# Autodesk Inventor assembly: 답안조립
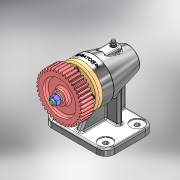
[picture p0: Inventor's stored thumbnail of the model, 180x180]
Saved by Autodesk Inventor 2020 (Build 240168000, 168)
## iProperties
Created: 2024-12
Part Number: 답안조립
Document SubType Name: Assembly
Designer: 1강의실14
Author: 1강의실14
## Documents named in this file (15)
- C:\Users\1강의실14\Desktop\741204V1013\답안조립.iam
- C:\Users\1강의실14\Desktop\741204V1013\본체.ipt
- C:\Users\1강의실14\Desktop\741204V1013\앵귤러 볼 베어링 7003A.ipt
- C:\Users\1강의실14\Desktop\741204V1013\축.ipt
- C:\Users\1강의실14\Desktop\741204V1013\앵귤러 볼 제어링 7204A.ipt
- C:\Users\1강의실14\Desktop\741204V1013\오일 실 20 32 8.ipt
- C:\Users\1강의실14\Desktop\741204V1013\육각 소켓 머리 볼트 M4x10.ipt
- C:\Users\1강의실14\Desktop\741204V1013\커버.ipt
- C:\Users\1강의실14\Desktop\741204V1013\스퍼기어.ipt
- C:\Users\1강의실14\Desktop\741204V1013\평행 키 4x4x14.ipt
- C:\Users\1강의실14\Desktop\741204V1013\스프링 와셔 M8.ipt
- C:\Users\1강의실14\Desktop\741204V1013\육각 너트 M8.ipt
- C:\Users\1강의실14\Desktop\741204V1013\평와셔 M8.ipt
- C:\Users\1강의실14\Desktop\741204V1013\그리스 니플 M6x0.75.ipt
- C:\Users\1강의실14\Desktop\741204V1013\실링.ipt
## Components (1 placed, 1 different names)
1. 그리스 니플 M6x0.75:1
